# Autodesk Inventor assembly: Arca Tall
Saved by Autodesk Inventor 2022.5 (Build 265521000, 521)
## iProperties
Created: 2024-07
Part Number: Arca Tall
Document SubType Name: Assembly
Designer: AdminForWorker
Title: Arca Tall v16
Author: AdminForWorker
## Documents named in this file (2)
- z:\worker\convert-fusion-r03-cosv3\tmp\job-1\56\temp\files\8d2a2a6e-beca-4914-beb0-95083099f5d5\Arca Tall v16.iam
- z:\worker\convert-fusion-r03-cosv3\tmp\job-1\56\temp\files\8d2a2a6e-beca-4914-beb0-95083099f5d5\Arca Tall - Balon v3.3.ipt
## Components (1 placed, 1 different names)
1. Arca Tall - Balon v3.3:1
